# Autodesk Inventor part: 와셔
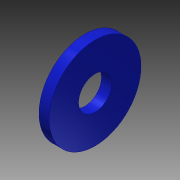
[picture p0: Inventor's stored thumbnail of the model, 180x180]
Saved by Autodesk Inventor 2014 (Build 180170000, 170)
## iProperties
Created: 2015-12
Part Number: 와셔
Material: 스테인리스강
Document SubType Name: Modeling
Designer: mduedu
Density: 8.08 g/cm^3
Mass: 3.57598 g
Surface Area: 5.9651 cm^2
Volume: 0.442572 cm^3
Appearance: 파란색 - 벽 페인트 - 광택
Author: mduedu
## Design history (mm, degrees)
sketch "스케치1"
  geometry: C1 r 3.25 at (0, 0); C2 r 9 at (0, 0); 1 further point
  constraints: 2 centre point, 2 coincident
  dimensions: "d0" = 6.5 diameter of C1; "d1" = 18 diameter of C2
extrude "돌출1" new body sketch "스케치1" stored distance "d2" = 2; taper "d3" = 0 deg
node "솔리드1"
